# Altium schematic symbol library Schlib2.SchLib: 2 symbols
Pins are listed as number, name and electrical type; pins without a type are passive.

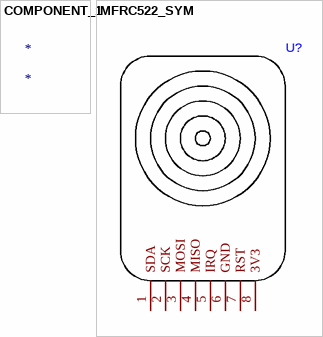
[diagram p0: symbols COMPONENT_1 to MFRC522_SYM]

## COMPONENT_1
designator *

## MFRC522_SYM
designator U?
footprint MFRC522_FURO
pins: 1 SDA, 2 SCK, 3 MOSI, 4 MISO, 5 IRQ, 6 GND, 7 RST, 8 3V3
